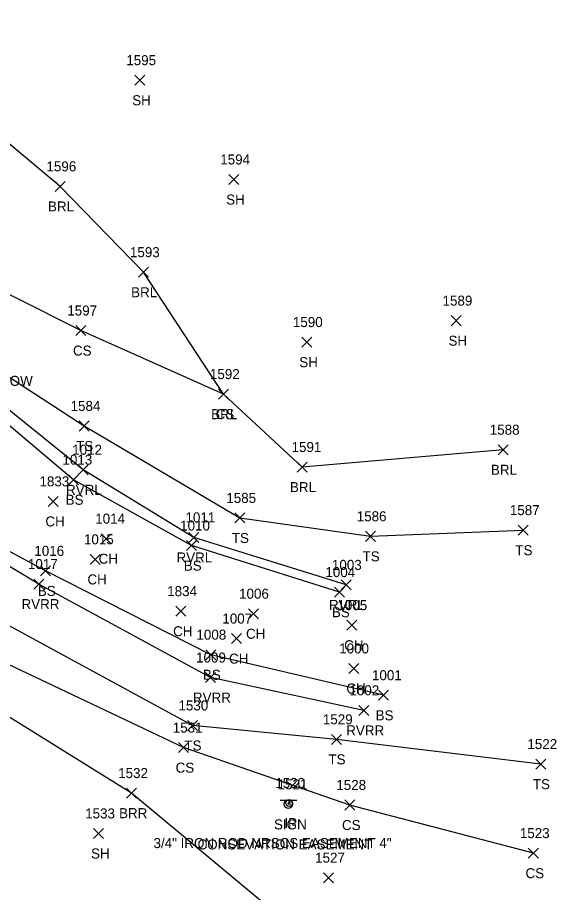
# Model space of a CAD drawing. Extents: x 1469310 to 1475157, y 493997 to 498873.
# Drawn here: x 1469708 to 1469815.6, y 498476.8 to 498651.4 of the extents above; entities that cross this region are included whole.
import ezdxf

# ---------------------------------------------------------------- set-up
doc = ezdxf.new("R2010")
doc.units = 0
for name, color, linetype in [('L_A', 7, 'Continuous'), ('L_C', 7, 'Continuous'), ('L_I', 7, 'Continuous'), ('L_TIC', 7, 'Continuous'), ('LABL', 7, 'Continuous'), ('LAWE', 7, 'Continuous'), ('LELB', 7, 'Continuous'), ('M_A', 7, 'Continuous'), ('M_C', 7, 'Continuous'), ('M_I', 7, 'Continuous'), ('MPIR', 7, 'Continuous'), ('S_A', 7, 'Continuous'), ('S_C', 7, 'Continuous'), ('S_I', 7, 'Continuous'), ('SSGN', 7, 'Continuous')]:
    doc.layers.add(name, color=color, linetype=linetype)

msp = doc.modelspace()

# ---------------------------------------------------------------- linework, layer by layer
at = {"layer": 'L_TIC'}
for points in [[(1469731.38, 498637.87), (1469733.38, 498639.87)], [(1469733.38, 498637.87), (1469731.38, 498639.87)], [(1469750.14, 498618.05), (1469752.14, 498620.05)], [(1469752.14, 498618.05), (1469750.14, 498620.05)], [(1469715.5, 498616.67), (1469717.5, 498618.67)], [(1469717.5, 498616.67), (1469715.5, 498618.67)], [(1469732.12, 498599.55), (1469734.12, 498601.55)], [(1469734.12, 498599.55), (1469732.12, 498601.55)], [(1469794.53, 498589.88), (1469796.53, 498591.88)], [(1469796.53, 498589.88), (1469794.53, 498591.88)], [(1469719.61, 498587.91), (1469721.61, 498589.91)], [(1469721.61, 498587.91), (1469719.61, 498589.91)], [(1469764.73, 498585.6), (1469766.73, 498587.6)], [(1469766.73, 498585.6), (1469764.73, 498587.6)], [(1469748.08, 498575.22), (1469750.08, 498577.22)], [(1469750.08, 498575.22), (1469748.08, 498577.22)], [(1469748.08, 498575.22), (1469750.08, 498577.22)], [(1469750.08, 498575.22), (1469748.08, 498577.22)], [(1469720.27, 498568.86), (1469722.27, 498570.86)], [(1469722.27, 498568.86), (1469720.27, 498570.86)], [(1469803.95, 498564.12), (1469805.95, 498566.12)], [(1469805.95, 498564.12), (1469803.95, 498566.12)], [(1469720.09, 498560.12), (1469722.09, 498562.12)], [(1469722.09, 498560.12), (1469720.09, 498562.12)], [(1469763.81, 498560.66), (1469765.81, 498562.66)], [(1469765.81, 498560.66), (1469763.81, 498562.66)], [(1469718.14, 498558.14), (1469720.14, 498560.14)], [(1469720.14, 498558.14), (1469718.14, 498560.14)], [(1469714.06, 498553.81), (1469716.06, 498555.81)], [(1469716.06, 498553.81), (1469714.06, 498555.81)], [(1469751.35, 498550.5), (1469753.35, 498552.5)], [(1469753.35, 498550.5), (1469751.35, 498552.5)], [(1469807.96, 498548.07), (1469809.96, 498550.07)], [(1469809.96, 498548.07), (1469807.96, 498550.07)], [(1469724.69, 498546.37), (1469726.69, 498548.37)], [(1469726.69, 498546.37), (1469724.69, 498548.37)], [(1469742.15, 498546.62), (1469744.15, 498548.62)], [(1469744.15, 498546.62), (1469742.15, 498548.62)], [(1469777.45, 498546.84), (1469779.45, 498548.84)], [(1469779.45, 498546.84), (1469777.45, 498548.84)], [(1469741.73, 498544.99), (1469743.73, 498546.99)], [(1469743.73, 498544.99), (1469741.73, 498546.99)], [(1469722.45, 498542.24), (1469724.45, 498544.24)], [(1469724.45, 498542.24), (1469722.45, 498544.24)], [(1469712.59, 498539.94), (1469714.59, 498541.94)], [(1469714.59, 498539.94), (1469712.59, 498541.94)], [(1469711.26, 498537.31), (1469713.26, 498539.31)], [(1469713.26, 498537.31), (1469711.26, 498539.31)], [(1469771.29, 498535.7), (1469773.29, 498537.7)], [(1469773.29, 498535.7), (1469771.29, 498537.7)], [(1469772.6, 498537.14), (1469774.6, 498539.14)], [(1469774.6, 498537.14), (1469772.6, 498539.14)], [(1469739.55, 498531.9), (1469741.55, 498533.9)], [(1469741.55, 498531.9), (1469739.55, 498533.9)], [(1469754.11, 498531.39), (1469756.11, 498533.39)], [(1469756.11, 498531.39), (1469754.11, 498533.39)], [(1469773.7, 498529.1), (1469775.7, 498531.1)], [(1469775.7, 498529.1), (1469773.7, 498531.1)], [(1469750.72, 498526.43), (1469752.72, 498528.43)], [(1469752.72, 498526.43), (1469750.72, 498528.43)], [(1469745.54, 498523.21), (1469747.54, 498525.21)], [(1469747.54, 498523.21), (1469745.54, 498525.21)], [(1469774.14, 498520.47), (1469776.14, 498522.47)], [(1469776.14, 498520.47), (1469774.14, 498522.47)], [(1469745.49, 498518.65), (1469747.49, 498520.65)], [(1469747.49, 498518.65), (1469745.49, 498520.65)], [(1469780.03, 498515.12), (1469782.03, 498517.12)], [(1469782.03, 498515.12), (1469780.03, 498517.12)], [(1469776.09, 498512.11), (1469778.09, 498514.11)], [(1469778.09, 498512.11), (1469776.09, 498514.11)], [(1469741.88, 498509.09), (1469743.88, 498511.09)], [(1469743.88, 498509.09), (1469741.88, 498511.09)], [(1469770.64, 498506.32), (1469772.64, 498508.32)], [(1469772.64, 498506.32), (1469770.64, 498508.32)], [(1469740.1, 498504.67), (1469742.1, 498506.67)], [(1469742.1, 498504.67), (1469740.1, 498506.67)], [(1469811.46, 498501.38), (1469813.46, 498503.38)], [(1469813.46, 498501.38), (1469811.46, 498503.38)], [(1469729.76, 498495.59), (1469731.76, 498497.59)], [(1469731.76, 498495.59), (1469729.76, 498497.59)], [(1469773.32, 498493.22), (1469775.32, 498495.22)], [(1469775.32, 498493.22), (1469773.32, 498495.22)], [(1469723.17, 498487.54), (1469725.17, 498489.54)], [(1469725.17, 498487.54), (1469723.17, 498489.54)], [(1469809.96, 498483.61), (1469811.96, 498485.61)], [(1469811.96, 498483.61), (1469809.96, 498485.61)], [(1469769.09, 498478.71), (1469771.09, 498480.71)], [(1469771.09, 498478.71), (1469769.09, 498480.71)]]:
    msp.add_lwpolyline(points, dxfattribs=at)
at = {"layer": 'LABL'}
for points in [[(1469804.95, 498565.12), (1469764.81, 498561.66), (1469749.08, 498576.22), (1469733.12, 498600.55), (1469716.5, 498617.67), (1469685.26, 498643.73), (1469661.91, 498654.33), (1469615.65, 498658), (1469588.27, 498643.44), (1469563.61, 498633.27)], [(1469812.4, 498427.83), (1469789.82, 498450.51), (1469762.16, 498470.41), (1469730.76, 498496.59), (1469695.43, 498518.47), (1469668.13, 498535.82), (1469658.49, 498545.19), (1469647.1, 498565.82), (1469633.19, 498572.64), (1469634.36, 498584.72)]]:
    msp.add_lwpolyline(points, dxfattribs=at)
at = {"layer": 'LAWE'}
for points in [[(1469773.6, 498538.14), (1469743.15, 498547.62), (1469721.09, 498561.12), (1469693.49, 498583.35), (1469669.75, 498607.46), (1469645.14, 498621.4), (1469610.76, 498626.27), (1469594.26, 498621.31), (1469595.4, 498613.66), (1469596.71, 498614.18)], [(1469777.09, 498513.11), (1469746.49, 498519.65), (1469712.26, 498538.31), (1469693.08, 498549.78), (1469666.06, 498566.65), (1469651.93, 498579.61), (1469627.93, 498592.68), (1469614.45, 498590.36), (1469606.53, 498592.03), (1469606.28, 498594.98), (1469607.18, 498595.59)]]:
    msp.add_lwpolyline(points, dxfattribs=at)
at = {"layer": 'LELB'}
for points in [[(1469749.08, 498576.22), (1469720.61, 498588.91), (1469694.2, 498602.15), (1469680.98, 498626.16), (1469659.92, 498645.28), (1469619.31, 498648.47), (1469591.69, 498636.4), (1469573.01, 498624.24)], [(1469600.59, 498604.32), (1469587.66, 498609.37), (1469585.47, 498618.1), (1469584.45, 498621.66), (1469592.04, 498627.25), (1469618.41, 498633.91), (1469636.49, 498631.42), (1469646.84, 498626.77), (1469675.4, 498609.13), (1469687.64, 498598.94), (1469700.03, 498583.67), (1469721.27, 498569.86), (1469752.35, 498551.5), (1469778.45, 498547.84), (1469808.96, 498549.07)], [(1469772.29, 498536.7), (1469742.73, 498545.99), (1469719.14, 498559.14), (1469691.2, 498582.67), (1469667.68, 498605.39), (1469646.54, 498618.87), (1469610.66, 498623.61), (1469596.02, 498618.19), (1469597.15, 498614.34), (1469602.07, 498605.37)], [(1469781.03, 498516.12), (1469746.54, 498524.21), (1469713.59, 498540.94), (1469693.44, 498551.74), (1469667.94, 498566.78), (1469651.72, 498581.21), (1469628.32, 498594.65), (1469613.89, 498590.69), (1469608.41, 498591.74), (1469608.46, 498595.93), (1469602.07, 498605.37)], [(1469812.46, 498502.38), (1469771.64, 498507.32), (1469742.88, 498510.09), (1469696.57, 498535.25), (1469676.26, 498550.53), (1469653, 498571.74), (1469634.36, 498584.72), (1469625.46, 498586.14), (1469614.78, 498575.79), (1469604.98, 498569.72)], [(1469810.96, 498484.61), (1469774.32, 498494.22), (1469741.1, 498505.67), (1469693.03, 498528.46), (1469673.62, 498546.03), (1469647.1, 498565.82), (1469633.56, 498558.77), (1469612.98, 498555.12)]]:
    msp.add_lwpolyline(points, dxfattribs=at)
at = {"layer": 'MPIR'}
msp.add_lwpolyline([(1469762.21, 498494.95), (1469761.93, 498494.45), (1469762.5, 498494.45)], close=True, dxfattribs=at)
msp.add_circle((1469762.21, 498494.62), 0.667, dxfattribs=at)
at = {"layer": 'SSGN'}
for p, q in [((1469760.4, 498495.2), (1469763.73, 498495.2)), ((1469762.04, 498494.37), (1469762.04, 498494.37))]:
    msp.add_line(p, q, dxfattribs=at)
msp.add_circle((1469762.04, 498494.37), 0.833, dxfattribs=at)

# ---------------------------------------------------------------- texts
at = {"layer": 'L_A'}
for s, p in [('SH', (1469730.87, 498633.87)), ('SH', (1469749.63, 498614.05)), ('BRL', (1469714.05, 498612.67)), ('BRL', (1469730.66, 498595.55)), ('SH', (1469794.02, 498585.88)), ('CS', (1469719.05, 498583.91)), ('SH', (1469764.22, 498581.6)), ('BRL', (1469746.63, 498571.22)), ('CS', (1469747.53, 498571.22)), ('TS', (1469719.68, 498564.86)), ('BRL', (1469802.49, 498560.12)), ('BRL', (1469762.36, 498556.66)), ('RVRL', (1469717.66, 498556.12)), ('BS', (1469717.58, 498554.14)), ('CH', (1469713.54, 498549.81)), ('TS', (1469750.76, 498546.5)), ('RVRL', (1469739.72, 498542.62)), ('TS', (1469776.86, 498542.84)), ('TS', (1469807.37, 498544.07)), ('CH', (1469724.18, 498542.37)), ('BS', (1469741.17, 498540.99)), ('CH', (1469721.94, 498538.24)), ('BS', (1469712.03, 498535.94)), ('RVRR', (1469708.77, 498533.31)), ('RVRL', (1469770.17, 498533.14)), ('BS', (1469770.74, 498531.7)), ('CH', (1469739.04, 498527.9)), ('CH', (1469753.6, 498527.39)), ('CH', (1469773.19, 498525.1)), ('CH', (1469750.21, 498522.43)), ('BS', (1469744.98, 498519.21)), ('CH', (1469773.63, 498516.47)), ('RVRR', (1469743, 498514.65)), ('BS', (1469779.47, 498511.12)), ('RVRR', (1469773.6, 498508.11)), ('TS', (1469741.29, 498505.09)), ('TS', (1469770.05, 498502.32)), ('CS', (1469739.54, 498500.67)), ('TS', (1469810.87, 498497.38)), ('BRR', (1469728.25, 498491.59)), ('CS', (1469772.76, 498489.22)), ('SH', (1469722.66, 498483.54)), ('CS', (1469809.4, 498479.61))]:
    msp.add_text(s, height=2, dxfattribs=at).set_placement(p)
at = {"layer": 'L_C'}
msp.add_text('2 L.WILLOW', height=2, dxfattribs=at).set_placement((1469695.71, 498577.87))
at = {"layer": 'L_I'}
for s, p in [('1595', (1469729.69, 498641.87)), ('1594', (1469748.45, 498622.05)), ('1596', (1469713.75, 498620.67)), ('1593', (1469730.42, 498603.55)), ('1589', (1469792.83, 498593.88)), ('1597', (1469717.91, 498591.91)), ('1590', (1469762.95, 498589.6)), ('1592', (1469746.39, 498579.22)), ('1592', (1469746.39, 498579.22)), ('1584', (1469718.57, 498572.86)), ('1588', (1469802.26, 498568.12)), ('1012', (1469718.89, 498564.12)), ('1591', (1469762.69, 498564.66)), ('1013', (1469716.94, 498562.14)), ('1833', (1469712.36, 498557.81)), ('1585', (1469749.66, 498554.5)), ('1587', (1469806.27, 498552.07)), ('1014', (1469723.49, 498550.37)), ('1011', (1469741.51, 498550.62)), ('1586', (1469775.7, 498550.84)), ('1010', (1469740.44, 498548.99)), ('1015', (1469721.24, 498546.24)), ('1016', (1469711.33, 498543.94)), ('1017', (1469710.05, 498541.31)), ('1003', (1469770.75, 498541.14)), ('1004', (1469769.44, 498539.7)), ('1834', (1469737.86, 498535.9)), ('1006', (1469752.21, 498535.39)), ('1005', (1469771.85, 498533.1)), ('1007', (1469748.87, 498530.43)), ('1008', (1469743.69, 498527.21)), ('1000', (1469772.2, 498524.47)), ('1009', (1469743.63, 498522.65)), ('1001', (1469778.74, 498519.12)), ('1002', (1469774.24, 498516.11)), ('1530', (1469740.11, 498513.09)), ('1529', (1469768.94, 498510.32)), ('1531', (1469738.97, 498508.67)), ('1522', (1469809.77, 498505.38)), ('1532', (1469728.07, 498499.59)), ('1528', (1469771.62, 498497.22)), ('1533', (1469721.48, 498491.54)), ('1523', (1469808.27, 498487.61)), ('1527', (1469767.39, 498482.71))]:
    msp.add_text(s, height=2, dxfattribs=at).set_placement(p)
at = {"layer": 'M_A'}
msp.add_text('IP', height=2, dxfattribs=at).set_placement((1469761.26, 498489.62))
at = {"layer": 'M_C'}
msp.add_text('3/4" IRON ROD NRSCS EASEMENT 4"', height=2, dxfattribs=at).set_placement((1469735.13, 498485.62))
at = {"layer": 'M_I'}
msp.add_text('1520', height=2, dxfattribs=at).set_placement((1469759.44, 498497.62))
at = {"layer": 'S_A'}
msp.add_text('SIGN', height=2, dxfattribs=at).set_placement((1469759.18, 498489.35))
at = {"layer": 'S_C'}
msp.add_text('CONSEVATION EASEMENT', height=2, dxfattribs=at).set_placement((1469743.91, 498485.35))
at = {"layer": 'S_I'}
msp.add_text('1521', height=2, dxfattribs=at).set_placement((1469759.9, 498497.35))

doc.saveas('drawing.dxf')
